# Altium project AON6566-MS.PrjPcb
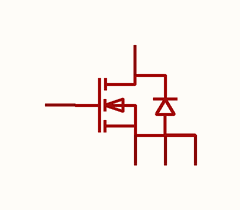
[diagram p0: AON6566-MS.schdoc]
1 sheet, 1 parts. Net scope: global (net labels, ports and power ports of the same name join across sheets).

## Sheet AON6566-MS.schdoc
size 127 x 101 mm

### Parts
Q?  aon6566-ms  [TDSON-8_L5.9-W5.2-P1.27-BL]  (value not drawn)

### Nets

Not connected (* = marked no-connect by the designer): Q? 1(S) 2(S) 3(S) 4(G) 5(D)

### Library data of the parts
Q? = aon6566-ms: 数量:1个N沟道;漏源电压(Vdss):-;连续漏极电流(Id):50A;导通电阻(RDS(on)):9mΩ@10V;耗散功率(Pd):-;阈值电压(Vgs(th)):2.5V@250uA;; Manufacturer: MSKSEMI(美森科); AddInBom: yes; ModelId: ff3d8edf19694f3eb1c5df98919f3bc8; ModelTransform: 216.9287,242.5192,0,0,0,0,0,43.307,0; Number: 1个N沟道; Current - Continuous Drain(Id): 50A; Gate Charge(Qg): 38nC@10V; Type: N沟道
